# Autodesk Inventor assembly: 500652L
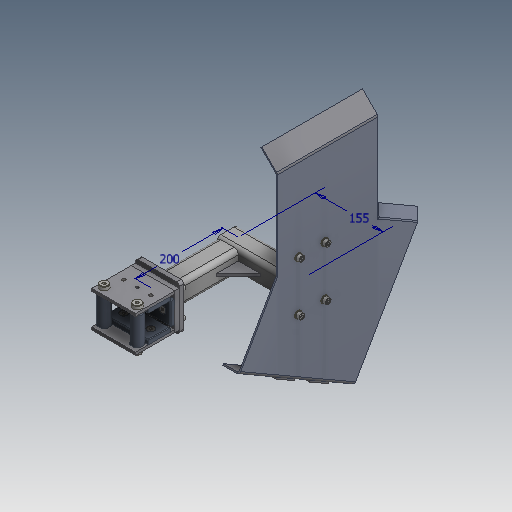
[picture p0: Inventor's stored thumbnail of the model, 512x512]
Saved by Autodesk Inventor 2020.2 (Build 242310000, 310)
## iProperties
Created: 2000-02
Part Number: 500652L
Document SubType Name: Assembly
Designer: sspink
Mass: 7970.97 g
Surface Area: 6473.94 cm^2
Volume: 1390.02 cm^3
Density: 5.73443 g/cm^3
Control State: 0
Master: False
Checked Out: False
Shininess: 0.0
Length Units: 11269
Angle Units: 11279
Time Units: 11290
Mass Units: 11283
Length Display Precision: 3
Angle Display Precision: 2
Compacted: True
Dimensions: 541,9x566,8x202,1 mm
Mass: 7,971 kg
DocNumber: 500652R.iam
Folder: 01 - Themengebiete\Simplification\01 - Packaging machine\
VDS_Category: 3D Komponenten
Density: 0.0
Volumn: 0.0
Area: 0.0
PropertySet Name: Model Information
Author: sspink
Revision Number: -
Title: 500652R
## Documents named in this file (15)
- D:\07 - DEMODATEN\OTX 2019 - Dataset - UPDATE - Dez2019\Designs\07-Packing machine\500652L.iam
- D:\07 - DEMODATEN\OTX 2019 - Dataset - UPDATE - Dez2019\Designs\07-Packing machine\500653.iam
- D:\07 - DEMODATEN\OTX 2019 - Dataset - UPDATE - Dez2019\Designs\07-Packing machine\Parts\ADSK-011631.ipt
- D:\07 - DEMODATEN\OTX 2019 - Dataset - UPDATE - Dez2019\Designs\07-Packing machine\Parts\ADSK-011632.ipt
- D:\07 - DEMODATEN\OTX 2019 - Dataset - UPDATE - Dez2019\Designs\07-Packing machine\Parts\ADSK-011728.ipt
- D:\07 - DEMODATEN\OTX 2019 - Dataset - UPDATE - Dez2019\Designs\07-Packing machine\Parts\ADSK-011664.ipt
- D:\07 - DEMODATEN\OTX 2019 - Dataset - UPDATE - Dez2019\Designs\07-Packing machine\500657.iam
- D:\07 - DEMODATEN\OTX 2019 - Dataset - UPDATE - Dez2019\Content Center Files\de-DE\ISO 10642(1)\ISO 10642 - M8x16.ipt
- D:\07 - DEMODATEN\OTX 2019 - Dataset - UPDATE - Dez2019\Content Center Files\de-DE\ISO 4032(1)\ISO 4032 - M10DIN EN.ipt
- D:\07 - DEMODATEN\OTX 2019 - Dataset - UPDATE - Dez2019\Content Center Files\de-DE\DIN 125-1  B\DIN 125-1 - B 8,4.ipt
- D:\07 - DEMODATEN\OTX 2019 - Dataset - UPDATE - Dez2019\Content Center Files\de-DE\ISO 4762(2)\ISO 4762 - M8 x 20ISO.ipt
- D:\07 - DEMODATEN\OTX 2019 - Dataset - UPDATE - Dez2019\Content Center Files\de-DE\DIN 125-1  B\DIN 125-1 - B 5,3.ipt
- D:\07 - DEMODATEN\OTX 2019 - Dataset - UPDATE - Dez2019\Content Center Files\de-DE\ISO 4762(2)\ISO 4762 - M5 x 12ISO.ipt
- D:\07 - DEMODATEN\OTX 2019 - Dataset - UPDATE - Dez2019\Designs\07-Packing machine\Parts\ADSK-011623.ipt
- D:\07 - DEMODATEN\OTX 2019 - Dataset - UPDATE - Dez2019\Content Center Files\de-DE\ISO 4032(1)\ISO 4032 - M8DIN EN.ipt
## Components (52 placed, 14 different names)
1. 500653:1 [sub-assembly] — Mate:1, Flush:2, Insert:1, Insert:2, Passend:24, Passend:25, Passend:26, Passend:27, Passend:28, Passend:29, Passend:30, Passend:31, Passend:32, Fluchtend:3, Passend:35, Passend:36, Passend:37, Passend:38, Passend:46, Passend:48
2. 500657:1 [sub-assembly] — Passend:24, Passend:25, Passend:26, Passend:50, Passend:56, Passend:58, Passend:60, Passend:108, Passend:109, Passend:110, Passend:118, Passend:120, Passend:122, Passend:124
3. ADSK-011631:1 — Passend:34, Fluchtend:3
4. ADSK-011631:2 — Passend:33, Passend:35
5. ADSK-011632:1 — Mate:1, Flush:2, Passend:27, Passend:28, Passend:29
6. ADSK-011632:2 — Passend:36, Passend:37, Passend:38
7. ADSK-011632:3 — Passend:30, Passend:31, Passend:32
8. ADSK-011728:1 — Insert:2, Passend:33
9. ADSK-011728:2 — Insert:1, Passend:34
10. ADSK-011623:1 — Passend:94, Passend:108, Passend:109, Passend:110, Passend:111, Passend:112, Passend:113, Passend:114, Passend:115, Passend:116
11. ADSK-011664:1 — Passend:111, Passend:112, Passend:116
12. ADSK-011664:2 — Passend:94, Passend:113, Passend:114, Passend:115
13. DIN 125-1 B B 5,3:7 — Passend:100, Passend:102
14. DIN 125-1 B B 5,3:8
15. ISO 4762 M5 x 12:5 — Passend:100
16. ISO 4762 M5 x 12:6 — Passend:102
17. DIN 125-1 B B 5,3:9 — Einfügen:29
18. DIN 125-1 B B 5,3:10 — Einfügen:30
19. ISO 4762 M5 x 12:7 — Einfügen:30
20. ISO 4762 M5 x 12:8 — Einfügen:29
21. DIN 125-1 B B 8,4:7 — Passend:118
22. DIN 125-1 B B 8,4:8 — Passend:120
23. DIN 125-1 B B 8,4:9 — Passend:122
24. DIN 125-1 B B 8,4:10 — Passend:124
25. DIN 125-1 B B 8,4:11
26. DIN 125-1 B B 8,4:12
27. DIN 125-1 B B 8,4:13
28. DIN 125-1 B B 8,4:14
29. DIN EN 24032 M8:1
30. DIN EN 24032 M8:2
31. DIN EN 24032 M8:3
32. DIN EN 24032 M8:4
33. ISO 4762 M8 x 20:7
34. ISO 4762 M8 x 20:8
35. ISO 4762 M8 x 20:9
36. ISO 4762 M8 x 20:10
37. ISO 4762 M8 x 20:6 — Passend:72
38. ISO 4762 M8 x 20:5 — Passend:70
39. ISO 4762 M8 x 20:4 — Passend:68
40. ISO 4762 M8 x 20:1 — Passend:62
41. DIN 125-1 B B 8,4:6 — Passend:60
42. DIN 125-1 B B 8,4:5 — Passend:58
43. DIN 125-1 B B 8,4:4 — Passend:56
44. DIN 125-1 B B 8,4:1 — Passend:50, Passend:62, Passend:68, Passend:70, Passend:72
45. ISO 10642 M8x16:1
46. ISO 10642 M8x16:2
47. ISO 10642 M8x16:3
48. ISO 10642 M8x16:4
49. ISO 10642 M8x16:5
50. ISO 10642 M8x16:6
51. DIN EN 24032 M10:1 — Passend:46
52. DIN EN 24032 M10:2 — Passend:48
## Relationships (48: Mate 42, Insert 4, Flush 2)
- Mate:1: 500653:1 ↔ ADSK-011632:1
- Flush:2: 500653:1 ↔ ADSK-011632:1
- Insert:1: 500653:1 ↔ ADSK-011728:2
- Insert:2: 500653:1 ↔ ADSK-011728:1
- Passend:24 [Mate]: 500653:1 ↔ 500657:1
- Passend:25 [Mate]: 500653:1 ↔ 500657:1
- Passend:26 [Mate]: 500653:1 ↔ 500657:1
- Passend:27 [Mate]: 500653:1 ↔ ADSK-011632:1
- Passend:28 [Mate]: 500653:1 ↔ ADSK-011632:1
- Passend:29 [Mate]: 500653:1 ↔ ADSK-011632:1
- Passend:30 [Mate]: 500653:1 ↔ ADSK-011632:3
- Passend:31 [Mate]: 500653:1 ↔ ADSK-011632:3
- Passend:32 [Mate]: 500653:1 ↔ ADSK-011632:3
- Passend:33 [Mate]: ADSK-011631:2 ↔ ADSK-011728:1
- Passend:34 [Mate]: ADSK-011631:1 ↔ ADSK-011728:2
- Fluchtend:3 [Flush]: 500653:1 ↔ ADSK-011631:1
- Passend:35 [Mate]: 500653:1 ↔ ADSK-011631:2
- Passend:36 [Mate]: 500653:1 ↔ ADSK-011632:2
- Passend:37 [Mate]: 500653:1 ↔ ADSK-011632:2
- Passend:38 [Mate]: 500653:1 ↔ ADSK-011632:2
- Passend:46 [Mate]: 500653:1 ↔ DIN EN 24032 M10:1
- Passend:48 [Mate]: 500653:1 ↔ DIN EN 24032 M10:2
- Passend:50 [Mate]: 500657:1 ↔ DIN 125-1 B B 8,4:1
- Passend:56 [Mate]: 500657:1 ↔ DIN 125-1 B B 8,4:4
- Passend:58 [Mate]: 500657:1 ↔ DIN 125-1 B B 8,4:5
- Passend:60 [Mate]: 500657:1 ↔ DIN 125-1 B B 8,4:6
- Passend:62 [Mate]: ISO 4762 M8 x 20:1 ↔ DIN 125-1 B B 8,4:1
- Passend:68 [Mate]: ISO 4762 M8 x 20:4 ↔ DIN 125-1 B B 8,4:1
- Passend:70 [Mate]: ISO 4762 M8 x 20:5 ↔ DIN 125-1 B B 8,4:1
- Passend:72 [Mate]: ISO 4762 M8 x 20:6 ↔ DIN 125-1 B B 8,4:1
- Passend:94 [Mate]: ADSK-011623:1 ↔ ADSK-011664:2
- Passend:100 [Mate]: DIN 125-1 B B 5,3:7 ↔ ISO 4762 M5 x 12:5
- Passend:102 [Mate]: DIN 125-1 B B 5,3:7 ↔ ISO 4762 M5 x 12:6
- Passend:108 [Mate]: 500657:1 ↔ ADSK-011623:1
- Passend:109 [Mate]: 500657:1 ↔ ADSK-011623:1
- Passend:110 [Mate]: 500657:1 ↔ ADSK-011623:1
- Passend:111 [Mate]: ADSK-011623:1 ↔ ADSK-011664:1
- Passend:112 [Mate]: ADSK-011623:1 ↔ ADSK-011664:1
- Passend:113 [Mate]: ADSK-011623:1 ↔ ADSK-011664:2
- Passend:114 [Mate]: ADSK-011623:1 ↔ ADSK-011664:2
- Passend:115 [Mate]: ADSK-011623:1 ↔ ADSK-011664:2
- Passend:116 [Mate]: ADSK-011623:1 ↔ ADSK-011664:1
- Einfügen:29 [Insert]: DIN 125-1 B B 5,3:9 ↔ ISO 4762 M5 x 12:8
- Einfügen:30 [Insert]: DIN 125-1 B B 5,3:10 ↔ ISO 4762 M5 x 12:7
- Passend:118 [Mate]: 500657:1 ↔ DIN 125-1 B B 8,4:7
- Passend:120 [Mate]: 500657:1 ↔ DIN 125-1 B B 8,4:8
- Passend:122 [Mate]: 500657:1 ↔ DIN 125-1 B B 8,4:9
- Passend:124 [Mate]: 500657:1 ↔ DIN 125-1 B B 8,4:10
